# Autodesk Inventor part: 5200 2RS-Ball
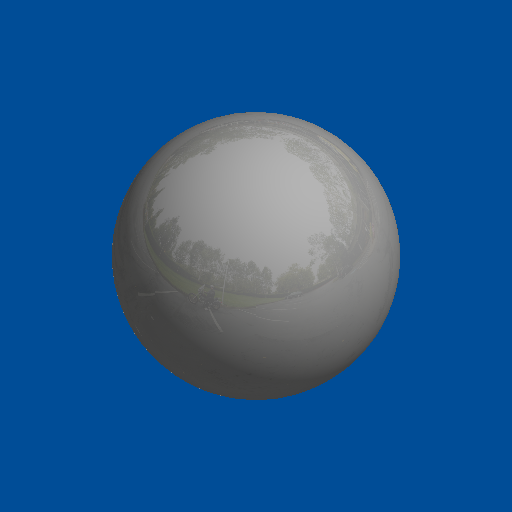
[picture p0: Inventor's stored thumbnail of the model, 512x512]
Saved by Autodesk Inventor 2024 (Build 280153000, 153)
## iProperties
Part Number: 5200 2RS-Ball
Material: Generic
Document SubType Name: Modeling
Designer: amoles
Appearance: Default
Author: amoles
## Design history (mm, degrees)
feature "5200 2RS-Ball"
body "Solid1"
